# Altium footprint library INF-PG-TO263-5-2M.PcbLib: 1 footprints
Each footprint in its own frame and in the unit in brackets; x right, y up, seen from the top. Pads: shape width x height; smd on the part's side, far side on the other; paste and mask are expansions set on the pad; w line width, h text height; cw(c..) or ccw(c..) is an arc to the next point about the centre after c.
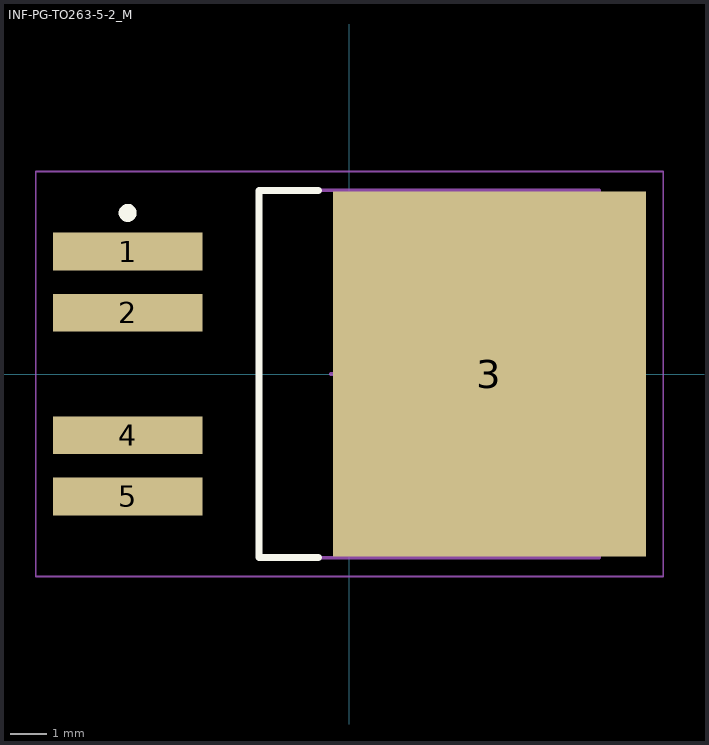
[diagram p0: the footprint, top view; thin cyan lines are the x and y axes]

## INF-PG-TO263-5-2_M [mm] "DPAK, 5-Leads, Body 10x9.25mm, Pitch 1.7mm, IPC Low Density"
height 4.4
pads (5):
  rect 4.15x1.05 smd: 1(-6.15,3.4) 2(-6.15,1.7) 4(-6.15,-1.7) 5(-6.15,-3.4)
  rect 8.7x10.15 smd: 3(3.9,0)
Top Overlay:
  circle w0.25: c-6.15,4.475 r0.125
  lines w0.2: -0.85,-5.1 -2.5,-5.1 -2.5,5.1 -0.85,5.1
Mechanical 13:
  lines w0.1: -2.5,-5.1 -2.5,5.1 6.95,5.1 6.95,-5.1 -2.5,-5.1
Mechanical 15:
  lines w0.05: -8.7,-5.625 -8.7,5.625 8.725,5.625 8.725,-5.625 -8.7,-5.625
  lines w0.1: -0.5,0 0.5,0 ; 0,-0.5 0,0.5
3D body: height 4.4, standoff 0.1, extent -2.5,-5.1 6.95,5.1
